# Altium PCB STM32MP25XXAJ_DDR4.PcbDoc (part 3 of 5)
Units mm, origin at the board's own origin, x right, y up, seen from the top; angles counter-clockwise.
Board outline 172 x 137 mm, 4 copper layers (Top Layer, Signal Layer 1, Signal Layer 2, Bottom Layer), stack 1.614 mm thick; 226 components, 313 nets, 1113 pads, 850 vias.
Unrouted connection lines stored in the file: 13.
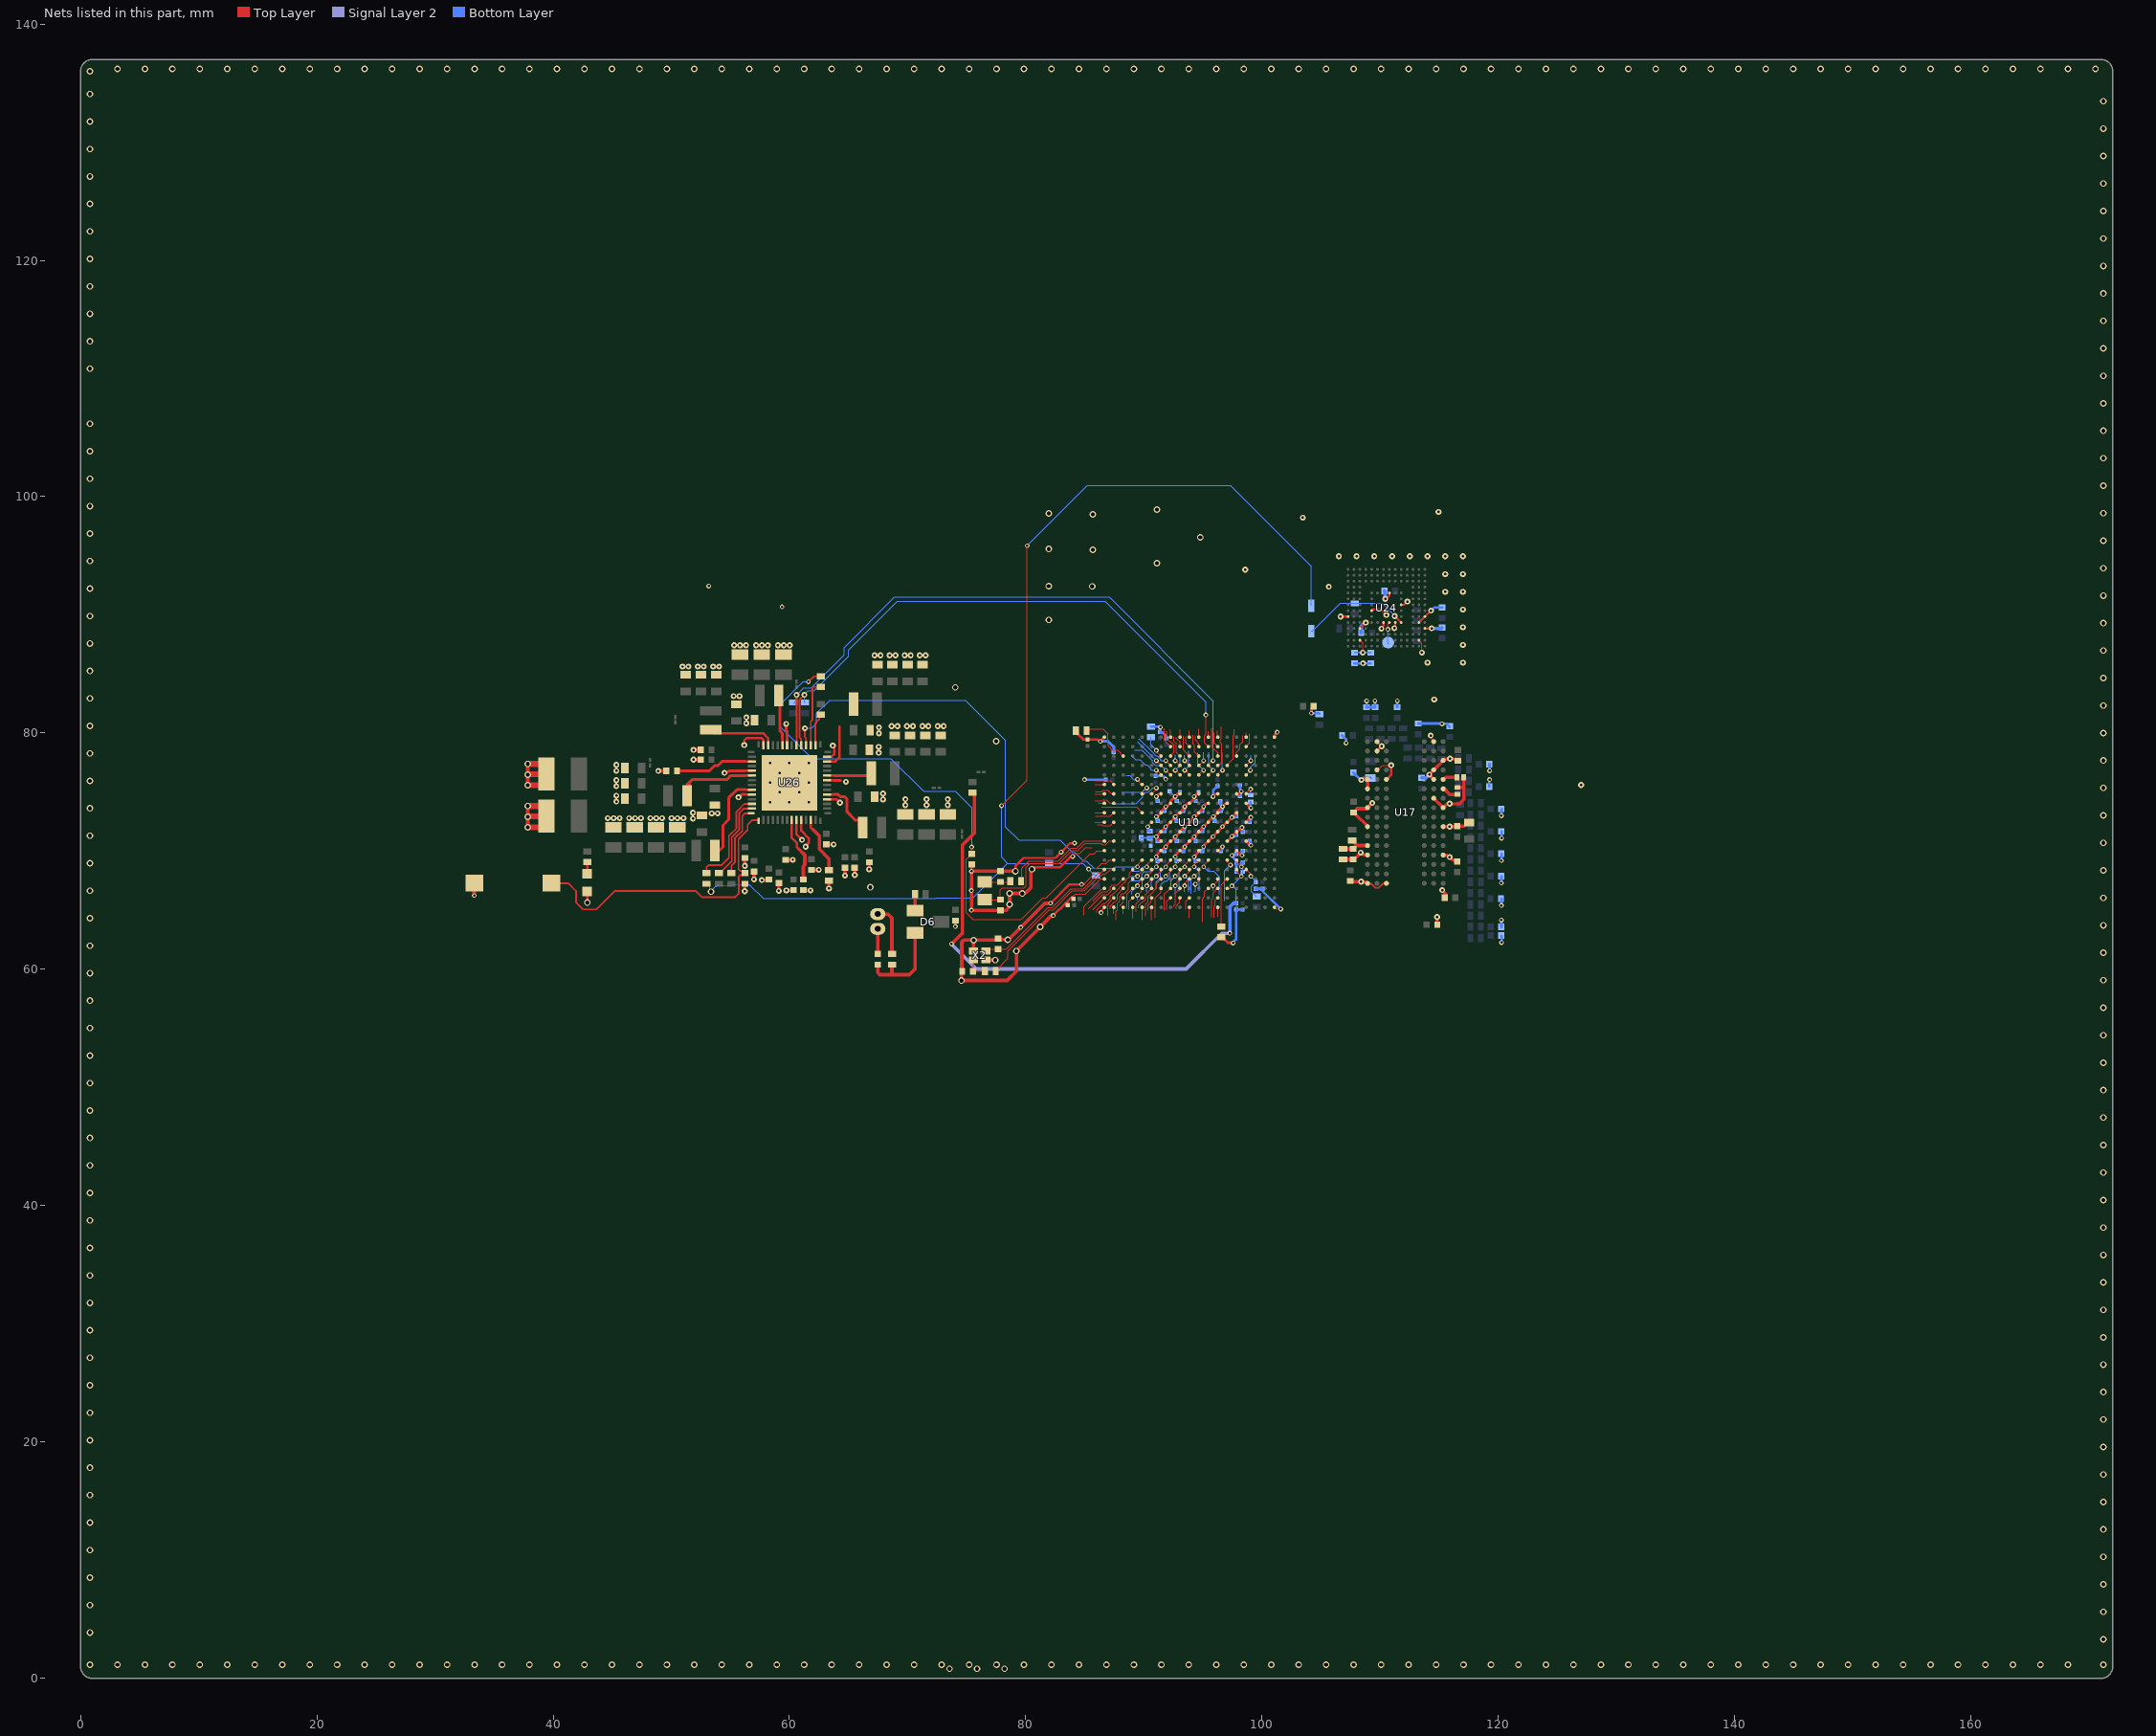
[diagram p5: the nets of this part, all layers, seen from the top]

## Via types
v1: diameter 0.55, hole 0.35, Top Layer to Bottom Layer, 344 vias
v2: diameter 0.5, hole 0.2, Top Layer to Bottom Layer, 250 vias
v3: diameter 0.4, hole 0.2, Top Layer to Bottom Layer, tented both sides, 180 vias
v4: diameter 0.4, hole 0.2, Top Layer to Bottom Layer, 76 vias

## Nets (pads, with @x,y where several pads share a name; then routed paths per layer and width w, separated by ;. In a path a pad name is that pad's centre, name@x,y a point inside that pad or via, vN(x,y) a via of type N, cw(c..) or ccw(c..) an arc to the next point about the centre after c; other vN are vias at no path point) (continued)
GND: B2.1 C18.2 C19.1 C20.1 C21.1 C22.1 C23.1 C24.1 C26.1 C27.1 C28.1 C29.1 C30.1 C32.1 C33.1 C34.1 C35.1 C36.1 C37.1 C38.1 C39.1 C40.1 C41.1 C42.2 C43.1 C67.1 C70.1 C79.1 C81.2 C82.1 C86.2 C87.1 C90.1 C91.2 C92.2 C94.1 C104.1 C105.1 C106.1 C112.1 C141.2 C142.2 C143.1 C144.1 C145.1 C146.1 C152.1 C153.1 C154.1 C155.1 C156.1 C157.1 C159.1 C160.1 C161.1 C163.1 C164.2 C165.1 C166.1 C167.1 C168.1 C169.1 C171.1 C172.1 C173.2 C174.2 C175.1 C176.1 C177.1 C178.1 C179.1 C180.1 C181.1 C182.1 C183.1 C184.1 C186.1 C187.1 C188.1 C189.1 C190.2 C191.2 C192.1 C193.1 C195.1 C196.1 C199.1 C200.1 C201.1 C202.1 C204.1 C206.1 C207.1 C208.2 C209.1 C210.1 C217.2 C218.1 C226.1 C239.1 C252.1 C254.1 C255.1 C256.1 C257.1 C258.1 C259.1 C261.1 C265.1 C266.1 C342.1 C344.1 C352.1 C353.1 C354.1 C355.1 C356.1 C357.1 C360.2 C372.1 C377.1 C378.1 C380.1 C381.1 C382.1 C383.1 C384.1 C386.1 C387.2 C388.1 C389.2 C390.1 C393.1 C399.2 C400.1 C402.1 C404.1 C406.1 C407.1 C408.1 C409.1 C417.1 C478.1 C479.1 C481.1 LD11.2 R57.1 R112.1 R113.1 R118.1 R161.2 R162.2 R176.1 R179.1 R196.1 U10.A1 U10.A19 U10.G7 U10.G9 U10.G11 U10.G13 U10.G15 U10.H8 U10.H10 U10.H12 U10.H14 U10.H16 U10.J7 U10.J9 U10.J11 U10.J13 U10.J15 U10.K8 U10.K10 U10.K12 U10.K14 U10.K16 U10.L7 U10.L9 U10.L11 U10.L13 U10.L15 U10.M7 U10.M8 U10.M10 U10.M12 U10.M14 U10.M16 U10.N7 U10.N9 U10.N11 U10.N13 U10.N15 U10.T1 U10.W1 U10.W19 U17.A2 U17.A8 U17.B2 U17.C9 U17.D2 U17.D8 U17.E1 U17.E3 U17.E8 U17.F1 U17.G8 U17.H1 U17.H9 U17.K1 U17.K9 U17.N1 U17.N9 U17.T1 U17.T3 U24.A6 U24.C4 U24.E7 U24.G5 U24.H10 U24.J5 U24.K8 U24.N2 U24.N5 U24.P4 U24.P6 U26.9 U26.10 U26.18 U26.22 U26.27 U26.36 U26.41 U26.47 U26.52 U26.57 X2.2 X2.4 | length 236.6
  Top Layer w0.09: U10.W19@101.05,65.25 101.058,65.25 101.208,65.1 v4(101.575,65.1) ; U24.N2@113.275,87.85 113.525,87.6 v2(113.525,86.8)
  Top Layer w0.1: v2@44.624,72.799 v2@44.625,72.8 ; X2.2@75.547,61.575 X2.2@75.548,61.576 ; v1@75.573,62.448 v1(75.587,62.462) v1@75.6,62.475 ; C406.1@83.9,66.1 84.185,66.385 85.068,66.385 86.333,67.65 U10.T1@86.65,67.65 ; v3(83.972,69.56) 84.237,69.825 84.544,69.825 85.034,70.315 85.6,70.315 ; 84.925,67.234 85.315,67.625 85.79,68.1 ; U17.D2@109.727,76.873 109.8,76.873 110.2,77.273 v2@110.927,77.273 ; v2(114.27,79.78) 114.27,79.672 114.37,79.572 114.37,79.494 114.525,79.339 U17.A8@114.525,79.275
  Top Layer w0.11: v4@86.291,64.884 U10.W1@86.65,65.244
  Top Layer w0.15: U17.T1@108.927,67.273 108.952,67.248 109.221,67.248 109.571,66.898 109.882,66.898 110.232,67.248 110.502,67.248 U17.T3@110.527,67.273
  Top Layer w0.18: v2(106.65,89.85) U24.A6@107.275,89.85 ; U24.C4@108.275,88.85 108.725,89.3 108.735,89.3 v2(108.775,89.34) ; U24.E7@109.275,90.35 109.283,90.35 109.416,90.483 110.028,90.483 110.516,89.995 v2(110.525,89.995) ; v2(110.1,88.825) 110.1,88.913 110.275,89.088 U24.G5@110.275,89.35 ; v2@110.425,91.275 110.775,91.625 U24.H10@110.775,91.85 ; v2(111.2,88.875) 111.2,88.962 111.275,89.037 U24.J5@111.275,89.35 ; U24.K8@111.775,90.85 112.025,90.85 v2(112.3,91.125) ; U24.N5@113.275,89.35 U24.P6@113.775,89.85 114.275,90.35 v2(114.3,90.35) ; U24.P4@113.775,88.85 v2(114.35,88.85)
  Top Layer w0.2: v1(42.887,65.648) LD11.2@42.887,66.577 ; U26.27@63.17,78 63.579,78 63.77,78.191 63.77,78.91 v2@63.816,78.956 ; v2(63.67,78.93) v2@63.727,78.873 ; C87.1@74.05,64.125 74.05,63.634 v3(74.051,63.633) ; v3(75.402,68.305) 75.416,68.319 C33.1@75.416,68.915 ; v1(79.125,68.3) 79.125,68.75 79.8,69.425 82.507,69.425 83.002,69.92 83.752,70.67 v4@84.121,70.67 ; v1(80.525,68.475) 80.62,68.475 80.795,68.65 82.912,68.65 83.784,69.522 v3@83.934,69.522 ; v3(82.1,65.6) 83.683,67.182 84.711,67.182 84.763,67.234 84.925,67.234 ; v3(82.325,64.55) 83.363,65.587 ; C67.1@83.55,65.425 83.525,65.425 83.363,65.587 ; C406.1@84.025,65.975 83.9,66.1 83.9,66.125 83.363,65.587 ; v4(91.05,69.525) 91.05,69.65 U10.N7@91.45,70.05 ; U10.N7@91.445,70.05 U10.N7@91.45,70.05 ; v3@91.85,70.438 91.462,70.05 U10.N7@91.45,70.05 ; v3@91.851,70.438 v3@91.863,70.438 ; v3(92.65,69.525) 92.709,69.584 92.709,69.709 U10.N9@93.05,70.05 93.125,70.05 v3(93.45,70.375) ; U17.E3@110.529,76.073 110.94,76.484 110.94,77.26 v2@110.927,77.273
  Top Layer w0.21: v2(56.175,78.975) 56.175,79.375 56.38,79.58 57.609,79.58 57.8,79.389 U26.41@57.8,78.97 ; 56.275,74.8 U26.52@56.83,74.8 ; 56.275,76.8 U26.47@56.83,76.8 ; U26.36@59.8,78.97 59.8,79.525 ; U26.9@60.6,72.63 60.6,71.42 v2(61.068,70.952) ; U26.10@61,72.63 61,71.734 61.635,71.099 61.635,70.72 61.37,70.456 v2(61.37,70.377) ; U26.18@63.17,74.4 63.972,74.4 v2(64.272,74.1) ; U26.22@63.17,76 63.725,76
  Top Layer w0.22: R162.2@84.25,80.2 84.395,80.055 84.395,79.914 84.854,79.455 85.22,79.455 C353.1@85.225,79.45 86.097,79.45 86.262,79.285 v4(86.31,79.285) 86.31,79.298 86.63,79.618 86.63,79.648 U10.A1@86.625,79.653 ; v3(91.05,71.225) 91.05,71.25 U10.L7@91.45,71.65 91.45,71.675 v3(91.85,72.075) ; v3(91.05,72.925) 91.084,72.959 91.164,72.959 U10.J7@91.45,73.245 ; v3@91.052,74.625 91.257,74.831 91.431,74.831 U10.G7@91.45,74.85 ; v3@91.07,71.146 91.112,71.146 91.393,70.865 91.393,70.85 U10.M7@91.445,70.85 ; U10.J7@91.45,73.25 91.465,73.265 91.465,73.404 v3@91.836,73.775 ; v3(91.85,70.375) 91.85,70.438 91.85,70.45 U10.M8@92.25,70.85 ; v3(91.85,73.775) 91.884,73.809 91.999,73.809 92.239,74.05 U10.H8@92.25,74.05 92.25,74.225 v3(92.65,74.625) 92.65,74.645 92.841,74.836 93.031,74.836 U10.G9@93.045,74.85 ; v3@91.875,72.075 U10.K8@92.25,72.45 92.65,72.85 v3(92.65,72.925) 92.65,72.939 92.894,73.183 92.926,73.183 92.993,73.25 U10.J9@93.05,73.25 93.425,73.625 v3@93.425,73.775 ; U10.M8@92.245,70.85 U10.M8@92.25,70.85 ; v4(92.65,71.225) 93.05,71.625 U10.L9@93.05,71.65 ; v4@92.698,71.18 92.637,71.18 92.307,70.85 U10.M8@92.25,70.85 ; U10.L9@93.045,71.65 93.348,71.954 93.441,71.954 93.441,72.046 U10.J11@94.647,73.253 ; v3(93.45,70.375) 93.45,70.45 U10.M10@93.85,70.85 93.875,70.85 v3(94.25,71.225) ; v3(93.45,73.775) 93.45,73.787 93.676,74.013 93.813,74.013 U10.H10@93.85,74.05 94.25,74.45 v3(94.25,74.625) 94.457,74.832 94.626,74.832 U10.G11@94.645,74.85 ; v3@94.225,69.525 94.65,69.95 U10.N11@94.65,70.05 ; v3@94.25,71.255 94.645,71.65 U10.L11@94.65,71.65 ; U10.J11@94.625,73.25 95.05,73.675 v3(95.05,73.775) 95.05,73.793 95.267,74.01 95.41,74.01 U10.H12@95.45,74.05 ; U10.L11@94.675,71.7 v4(95.05,72.075) ; v4(95.05,70.375) 95.084,70.409 95.084,70.484 U10.M12@95.45,70.85 95.825,71.225 v4(95.85,71.225) 95.85,71.253 U10.L13@96.247,71.65 ; v4@95.075,72.075 U10.K12@95.45,72.45 95.465,72.465 95.465,72.535 95.845,72.915 95.909,72.915 U10.J13@96.245,73.25 ; v3(95.85,74.625) 95.85,74.638 96.05,74.838 96.238,74.838 U10.G13@96.25,74.85 ; U10.N13@96.246,70.05 96.325,70.05 v3(96.65,70.375) ; U10.L13@96.25,71.661 v4@96.65,72.061 ; U10.J13@96.25,73.25 96.25,73.375 v3(96.65,73.775) ; R196.1@96.55,62.725 96.645,62.725 97.111,62.259 97.516,62.259 v4(97.55,62.225) ; v4(96.65,72.075) 97.025,72.45 U10.K14@97.05,72.45 ; v3@96.65,73.781 96.878,74.01 97.01,74.01 U10.H14@97.05,74.05 ; U10.M14@97.052,70.85 v3@97.45,71.248 ; U10.K14@97.052,72.45 v4@97.45,72.848 ; v4@97.45,72.854 U10.J15@97.846,73.25 ; v3@97.484,71.284 U10.L15@97.85,71.65 97.9,71.65 v3@98.25,72 ; U10.N15@97.835,70.035 U10.N15@97.85,70.05 ; U10.N15@97.85,70.049 v4@98.249,69.65 ; U10.G15@97.85,74.85 98.04,74.85 v3(98.25,75.06) ; U10.K16@98.65,72.45 v3(99.05,72.85) ; U10.H16@98.65,74.05 v3(99.05,73.65) ; U10.M16@98.652,70.85 99.002,70.5 v3(99.05,70.5) ; U10.A19@101.05,79.65 101.065,79.665 101.065,79.818 101.268,80.021 v4(101.268,80.062) ; v4(104.175,81.675) 104.175,82.05 C70.1@104.375,82.25 ; U17.B2@109.725,78.475 v2(110.125,78.875) U17.A2@109.725,79.275
  Top Layer w0.25: v2(54.508,76.625) 54.556,76.673 54.757,76.673 54.884,76.8 56.275,76.8 ; v2(55.687,74.563) 55.721,74.563 55.959,74.8 56.275,74.8 ; v2(59.725,80.775) 59.725,80.214 59.8,80.139 59.8,79.525 ; 63.725,76 64.33,76 ; v2@64.257,74.1 v2(64.272,74.1)
  Top Layer w0.28: C105.1@107.89,73.142 108.925,72.107 U17.K1@108.925,72.075 ; v2@108.377,76.073 108.927,76.073 U17.F1@108.927,75.273 ; U17.G8@114.525,74.475 U17.H9@115.325,73.675 115.674,74.025 v2(115.875,74.025) ; U17.E8@114.537,76.083 114.529,76.083 114.15,76.462 v2(114.15,76.475) 114.15,76.488 114.527,76.864 114.527,76.873 115.327,77.673 115.365,77.673 115.472,77.781 115.788,77.781 v2@115.83,77.823 ; C82.1@114.812,63.768 v2@114.812,64.413 ; U17.N9@115.327,69.673 115.353,69.646 115.669,69.646 v2@115.817,69.498 ; U17.K9@115.327,72.073 v2@115.877,72.073 ; v2@115.825,74 116.7,74 117.075,74.375 117.075,75.4 ; v2@115.877,69.498 115.886,69.498 116.151,69.233 116.402,69.233 C252.1@116.515,69.12 C252.1@116.515,69.12 ; v2@115.877,77.823 115.902,77.823 v2(115.9,77.825) 115.917,77.809 116.271,77.809 116.315,77.765 116.46,77.765 C178.1@116.575,77.65 ; v2@115.915,72.035 v2@115.877,72.073 ; R179.1@116.525,75.4 117.075,75.4 ; R113.1@117.075,76.25 117.075,75.4 ; C112.1@117.547,72.428 117.422,72.428 117.112,72.118 116.517,72.118 116.494,72.096 115.899,72.096 v2@115.877,72.073
  Top Layer w0.3: v3(33.319,66.245) 33.324,66.25 33.324,67.279 B2.1@33.34,67.295 ; v1(37.848,72.014) v1(37.848,72.914) v1(37.848,73.814) ; v1(37.848,75.576) v1(37.848,76.476) v1(37.848,77.376) ; v2(48.895,76.79) C43.1@49.555,76.79 ; v2(51.885,77.75) C40.1@52.495,77.75 ; v2(51.885,78.575) C39.1@52.495,78.575 ; v2@56.225,68.81 C217.2@56.225,69.42 ; v2@56.227,66.58 C155.1@56.227,67.185 ; v2(57,67.61) C154.1@57,68.215 ; v2(57.665,67.55) C142.2@58.275,67.55 ; v2@59.1,66.69 C141.2@59.1,67.3 ; C153.1@59.675,69.27 v2(60.285,69.27) ; v2(59.74,66.68) C91.2@60.35,66.68 ; C208.2@61.175,66.68 v2(61.785,66.68) ; C209.1@61.85,68.42 v2(62.485,68.42) ; C156.1@63.125,70.57 v2(63.735,70.57) ; v2(63.35,66.84) R57.1@63.35,67.5 ; v2(64.7,67.93) C189.1@64.7,68.59 ; v2(65.525,67.99) C188.1@65.525,68.59 C188.1@65.525,68.65 ; v2@66.75,68.465 66.747,68.467 66.747,69.063 C190.2@66.75,69.065 ; C92.2@74.563,59.875 74.563,59.087 74.588,59.063 78.438,59.063 79.225,59.85 79.225,61.525 v1(79.2,61.55) 81.225,63.575 v1(81.225,63.6) 82.156,64.531 82.306,64.531 v3(82.325,64.55) ; C92.2@74.625,59.825 74.576,59.874 74.576,62.299 74.752,62.475 75.6,62.475 76,62.475 76.013,62.488 76.663,62.488 76.675,62.475 77.5,62.475 77.625,62.6 C90.1@77.65,62.6 77.736,62.514 v1@78.475,62.514 ; v3(75.4,65) C86.2@77.85,65 ; 75.4,65.275 v3@75.4,66.65 ; v3@75.4,68.3 v3@75.402,68.3 ; v3(75.402,66.655) v3@75.402,68.3 ; v3(75.402,68.305) v3@75.402,68.3 ; X2.2@75.573,61.551 v1@75.573,62.448 ; X2.4@76.66,60.788 76.667,60.794 77.408,60.794 v1(77.415,60.788) ; C86.2@77.955,65.105 C86.2@77.85,65 ; v1(78.475,62.5) 78.525,62.5 v3(79.575,63.55) 81.606,65.581 v3@82.081,65.581 ; v1(79.125,68.3) C81.2@77.85,68.3 v3@75.402,68.3 ; v1(80.525,68.475) 80.43,68.38 80.43,66.905 79.993,66.468 79.748,66.468 v1(79.7,66.42) 79.695,66.425 v1(78.625,66.425) v1(78.625,65.5) 78.578,65.452 78.578,65.239 78.339,65 C86.2@77.85,65 ; R118.1@106.857,69.298 107.727,69.298 107.832,69.403 107.88,69.403 v2@108.354,69.877 ; C104.1@107.397,67.408 107.412,67.423 108.387,67.423 108.425,67.385 108.782,67.385 108.894,67.273 U17.T1@108.927,67.273 ; C105.1@107.737,73.278 C105.1@107.89,73.278 ; C105.1@107.75,73.275 107.775,73.275 107.88,73.38 107.88,73.405 108.07,73.595 108.812,73.595 108.89,73.673 108.927,73.673 v2@109.327,74.073 ; v2@108.355,69.878 108.409,69.878 108.591,69.696 108.904,69.696 U17.N1@108.925,69.675 U17.N1@108.927,69.673 ; v2(115.25,66.7) 115.25,66.646 115.552,66.344 C106.1@115.552,66.198
  Top Layer w0.5: v1(37.848,72.014) 39.39,72.014 C18.2@39.437,72.061 ; v1(37.848,72.914) 37.862,72.914 37.909,72.961 C18.2@39.437,72.961 ; v1(37.848,73.814) C18.2@39.379,73.814 ; v1(37.848,75.576) 39.39,75.576 C42.2@39.437,75.623 ; v1(37.848,76.476) 37.862,76.476 37.909,76.523 C42.2@39.437,76.523 ; v1(37.848,77.376) C42.2@39.379,77.376
  Bottom Layer w0.09: C404.1@99.95,66.725 C404.1@99.95,66.825
  Bottom Layer w0.1: C79.1@89.6,70.975 C79.1@89.689,70.975 ; C171.1@92.175,75.075 92.625,74.625 v3(92.65,74.625) ; v3@92.625,74.65 v3@92.7,74.65
  Bottom Layer w0.2: C79.1@89.75,71.125 90.5,71.125 90.525,71.1 C384.1@90.55,71.075 ; v4(91.05,69.525) 91.05,69.275 C399.2@91.175,69.15 ; v3(92.65,69.525) 92.65,69.25 C400.1@92.775,69.125 ; C404.1@99.95,66.725 v4(101.575,65.1) ; C182.1@107.825,85.9 v2(108.55,85.9) 109.175,85.9 C481.1@109.2,85.875 ; v2(114.3,90.35) 114.575,90.625 C478.1@115.225,90.625 C478.1@115.25,90.625
  Bottom Layer w0.22: v4@84.95,76.05 C161.1@86.775,76.05 ; v4(86.31,79.285) 86.325,79.3 86.95,79.3 87.45,78.8 C356.1@87.45,78.4 ; C384.1@90.5,71.075 90.65,71.225 v3(91.05,71.225) ; R161.2@90.6,80.55 91.35,80.55 v4@91.4,80.5 ; v4@90.975,69.5 v4@91.025,69.5 ; C344.1@90.975,76.375 91.575,76.375 v4(91.85,76.1) ; v3@91.016,71.191 v3(91.05,71.225) ; v3(91.05,72.925) 91.05,72.7 C169.1@91.2,72.55 ; v3(91.05,74.625) 91.05,74.576 91.11,74.516 91.11,74.315 C166.1@91.175,74.25 ; C387.2@91.175,70.85 91.05,70.975 v3(91.05,71.225) ; v4(91.403,80.496) 91.403,80.047 91.415,80.035 91.596,80.035 91.835,79.796 91.835,79.615 C352.1@91.9,79.55 ; C393.1@91.725,70.025 91.85,70.15 v3(91.85,70.375) ; C378.1@91.725,71.7 91.85,71.825 v3(91.85,72.075) ; C173.2@91.725,73.425 91.85,73.55 v3(91.85,73.775) ; v4(92.65,71.225) 92.65,70.975 C380.1@92.775,70.85 ; v3(92.65,72.925) 92.65,72.675 C164.2@92.775,72.55 ; C390.1@92.775,74.275 92.65,74.4 v3(92.65,74.625) 92.675,74.625 92.7,74.65 C143.1@93.05,75 ; C192.1@93.325,70 93.45,70.125 v3(93.45,70.375) ; C372.1@93.325,71.7 93.45,71.825 v3(93.45,72.075) ; C167.1@93.325,73.4 93.45,73.525 v3(93.45,73.775) ; v3(94.25,69.525) 94.25,69.275 C402.1@94.375,69.15 C402.1@94.4,69.125 ; v3(94.25,71.225) 94.25,70.975 C382.1@94.375,70.85 ; v4(94.25,72.925) 94.25,72.675 C168.1@94.375,72.55 ; v3(94.25,74.625) 94.25,74.375 C360.2@94.375,74.25 ; C381.1@94.925,70 95.05,70.125 v4(95.05,70.375) ; C388.1@94.925,71.7 95.05,71.825 v4(95.05,72.075) ; C159.1@94.925,73.4 95.05,73.525 v3(95.05,73.775) ; v3(95.85,74.625) 95.85,75.125 C354.1@96.225,75.5 ; v3(95.875,72.925) 95.875,72.65 C163.1@95.975,72.55 ; C165.1@96.475,74.225 96.475,73.95 v3(96.65,73.775) 96.65,73.525 C174.2@96.525,73.4 ; C191.2@96.525,70.025 96.65,70.15 v3(96.65,70.375) ; v4(97.45,72.85) 97.7,72.85 C201.1@97.825,72.975 C201.1@97.85,73 ; v3(97.45,71.25) 97.7,71.25 C377.1@97.825,71.375 ; v4(97.55,62.225) 97.55,62.274 97.8,62.524 C407.1@97.8,65.05 C210.1@98.35,65.05 ; C386.1@97.802,69.752 97.76,69.71 97.559,69.71 97.499,69.65 v3(97.45,69.65) 97.484,69.616 97.484,69.529 97.76,69.253 97.76,69.115 97.825,69.05 97.825,68.275 C417.1@97.85,68.25 ; C176.1@98.125,74.675 98.19,74.74 98.19,74.951 98.25,75.011 v3(98.25,75.06) 98.125,75.185 C357.1@98.125,75.575 C357.1@98.125,75.6 ; v4@98.25,69.65 98.25,69.9 C195.1@98.375,70.025 ; v3(98.3,72) 98.334,71.966 98.334,71.69 C383.1@98.399,71.625 ; C389.2@98.925,70.875 99.05,70.75 v3(99.05,70.5) ; C175.1@98.925,72.475 99.05,72.6 v3(99.05,72.85) ; R112.1@99.028,74.15 99.028,73.622 v3@99.05,73.6 ; v4(104.175,81.675) 104.8,81.675 R176.1@104.85,81.625 ; C255.1@106.775,79.8 106.775,79.775 106.92,79.63 106.945,79.63 107.109,79.466 107.109,79.166 v4(107.114,79.161) ; C218.1@107.725,76.65 108.35,76.025 v2(108.395,76.025) v2@108.4,76.025 ; v2@108.425,76.025 108.6,76.2 C172.1@109.175,76.2 ; C145.1@108.825,82.175 C145.1@108.85,82.175 ; v4(108.85,82.725) C145.1@108.85,82.175 ; v4(109.55,82.725) 109.562,82.713 109.562,82.188 C144.1@109.575,82.175 C145.1@108.85,82.175 ; C258.1@111.425,82.175 111.437,82.187 111.437,82.712 v4(111.45,82.725) ; C256.1@113.225,80.8 115.15,80.8 v4@115.2,80.75 ; v4(115.225,80.775) 115.625,80.775 C146.1@115.875,80.525 ; C257.1@119.225,75.475 119.225,75.975 v4@119.275,76.025 ; v4(119.25,76.8) C259.1@119.25,77.375 ; C254.1@120.25,62.825 120.275,62.8 v4(120.275,62.275) ; v4(120.25,64.175) C160.1@120.25,63.6 C160.1@120.275,63.575 ; v4(120.25,65.4) C226.1@120.25,65.975 ; v4(120.25,67.3) 120.25,67.85 C266.1@120.275,67.875 ; v4(120.25,69.2) 120.275,69.225 C239.1@120.275,69.75 ; v4(120.25,73) 120.25,73.5 C261.1@120.3,73.55 ; v4(120.275,71.1) C265.1@120.275,71.675
  Bottom Layer w0.28: C408.1@99.475,66.8 C404.1@100.025,66.8 ; C404.1@99.95,66.825 C404.1@99.975,66.825 ; C179.1@113.5,76.2 113.875,76.2 v2(114.15,76.475)
  Bottom Layer w0.3: C180.1@108.4,88.475 108.4,89.049 108.643,89.292 108.727,89.292 v2(108.775,89.34) ; C177.1@110.35,92.025 110.425,91.95 v2@110.425,91.275 ; v2(114.35,88.85) 115.15,88.85 C479.1@115.225,88.925
  other v1: 73.55,0.8 75.875,0.8 78.2,0.8 0.8,1.15 3.125,1.15 5.45,1.15 7.775,1.15 10.1,1.15 12.425,1.15 14.75,1.15 17.075,1.15 19.4,1.15 21.725,1.15 24.05,1.15 26.375,1.15 28.7,1.15 31.025,1.15 33.35,1.15 35.675,1.15 38,1.15 40.325,1.15 42.65,1.15 44.975,1.15 47.3,1.15 49.625,1.15 51.95,1.15 54.275,1.15 56.6,1.15 58.925,1.15 61.25,1.15 63.575,1.15 65.9,1.15 68.225,1.15 70.55,1.15 72.875,1.15 75.2,1.15 77.525,1.15 79.85,1.15 82.175,1.15 84.5,1.15 86.825,1.15 89.15,1.15 91.475,1.15 93.8,1.15 96.125,1.15 98.45,1.15 100.775,1.15 103.1,1.15 105.425,1.15 107.75,1.15 110.075,1.15 112.4,1.15 114.725,1.15 117.05,1.15 119.375,1.15 121.7,1.15 124.025,1.15 126.35,1.15 128.675,1.15 131,1.15 133.325,1.15 135.65,1.15 137.975,1.15 140.3,1.15 142.625,1.15 144.95,1.15 147.275,1.15 149.6,1.15 151.925,1.15 154.25,1.15 156.575,1.15 158.9,1.15 161.225,1.15 163.55,1.15 165.875,1.15 168.2,1.15 171.2,1.15 171.2,3.3 0.8,3.875 171.2,5.625 0.8,6.2 171.2,7.95 0.8,8.525 171.2,10.275 0.8,10.85 171.2,12.6 0.8,13.175 171.2,14.925 0.8,15.5 171.2,17.25 0.8,17.825 171.2,19.575 0.8,20.15 171.2,21.9 0.8,22.475 171.2,24.225 0.8,24.8 171.2,26.55 0.8,27.125 171.2,28.85 0.8,29.45 171.2,31.175 0.8,31.775 171.2,33.5 0.8,34.1 171.2,35.825 0.8,36.425 171.2,38.15 0.8,38.75 171.2,40.475 0.8,41.075 171.2,42.8 0.8,43.4 171.2,45.125 0.8,45.725 171.2,47.45 0.8,48.05 171.2,49.775 0.8,50.375 171.2,52.1 0.8,52.7 171.2,54.425 0.8,55.025 171.2,56.75 0.8,57.35 74.563,59.05 171.2,59.075 0.8,59.675 171.2,61.4 0.8,62 171.2,63.725 0.8,64.325 171.2,66.05 0.8,66.65 66.85,66.945 171.2,68.375 0.8,68.975 171.2,70.7 0.8,71.3 171.2,73.025 0.8,73.625 171.2,75.35 0.8,75.95 171.2,77.675 0.8,78.275 77.495,79.305 171.2,80 0.8,80.6 171.2,82.325 0.8,82.925 74.035,83.865 171.2,84.65 0.8,85.25 171.2,86.975 0.8,87.575 171.2,89.3 81.95,89.575 0.8,89.9 171.2,91.625 0.8,92.225 85.625,92.4 81.941,92.431 171.2,93.95 91.1,94.375 0.8,94.55 85.675,95.5 81.95,95.575 171.2,96.275 94.775,96.55 0.8,96.875 85.675,98.5 81.95,98.575 171.2,98.6 91.1,98.9 0.8,99.2 171.2,100.925 0.8,101.525 171.2,103.25 0.8,103.85 171.2,105.575 0.8,106.175 171.2,107.9 171.2,110.225 0.8,110.825 171.2,112.55 0.8,113.15 171.2,114.875 0.8,115.475 171.2,117.2 0.8,117.8 171.2,119.525 0.8,120.125 171.2,121.85 0.8,122.45 171.2,124.175 0.8,124.775 171.2,126.5 0.8,127.1 171.2,128.825 0.8,129.425 171.2,131.15 0.8,131.75 171.2,133.475 0.8,134.075 0.8,136 3.125,136.2 5.45,136.2 7.775,136.2 10.1,136.2 12.425,136.2 14.75,136.2 17.075,136.2 19.4,136.2 21.725,136.2 24.05,136.2 26.375,136.2 28.7,136.2 31.025,136.2 33.35,136.2 35.675,136.2 38,136.2 40.325,136.2 42.65,136.2 44.975,136.2 47.3,136.2 49.625,136.2 51.95,136.2 54.275,136.2 56.6,136.2 58.925,136.2 61.25,136.2 63.575,136.2 65.9,136.2 68.225,136.2 70.55,136.2 72.875,136.2 75.2,136.2 77.525,136.2 79.85,136.2 82.175,136.2 84.5,136.2 86.825,136.2 89.15,136.2 91.475,136.2 93.8,136.2 96.125,136.2 98.45,136.2 100.775,136.2 103.1,136.2 105.425,136.2 107.75,136.2 110.075,136.2 112.4,136.2 114.725,136.2 117.05,136.2 119.375,136.2 121.7,136.2 124.025,136.2 126.35,136.2 128.675,136.2 131,136.2 133.325,136.2 135.65,136.2 137.975,136.2 140.3,136.2 142.625,136.2 144.95,136.2 147.275,136.2 149.6,136.2 151.925,136.2 154.25,136.2 156.575,136.2 158.9,136.2 161.225,136.2 163.55,136.2 165.875,136.2 168.2,136.2 170.525,136.2
  other v2: 114.815,64.42 56.222,66.61 59.1,66.64 108.385,67.425 66.745,68.46 56.225,68.76 115.875,69.5 108.345,69.872 115.875,72.075 51.825,72.75 44.624,72.798 45.125,72.798 45.626,72.798 46.424,72.798 46.925,72.798 47.426,72.798 48.224,72.798 48.725,72.798 49.226,72.798 50.024,72.798 50.525,72.798 51.026,72.798 53.424,73.202 53.925,73.202 51.825,73.25 69.804,73.9 71.604,73.9 73.404,73.9 109.325,74.075 58.35,74.15 60,74.15 61.65,74.15 45.35,74.2 67.92,74.375 69.804,74.401 71.604,74.401 73.404,74.401 45.35,74.7 67.92,74.875 59.175,74.975 60.825,74.975 45.35,75.5 127,75.6 58.35,75.8 60,75.8 61.65,75.8 64.78,75.875 45.35,76 59.175,76.625 60.825,76.625 45.35,76.8 110.925,77.275 45.35,77.3 58.35,77.45 60,77.45 61.65,77.45 67.55,78.325 67.55,78.825 67.575,79.975 67.575,80.475 68.65,80.575 69.15,80.575 69.95,80.575 70.45,80.575 71.25,80.575 71.75,80.575 72.55,80.575 73.05,80.575 56.35,80.823 56.35,81.323 114.562,82.831 55.275,83.123 55.776,83.123 50.95,85.623 51.451,85.623 52.25,85.623 52.751,85.623 53.55,85.623 54.051,85.623 114,85.95 117,85.95 67.2,86.575 67.7,86.575 68.475,86.575 68.975,86.575 69.75,86.575 70.25,86.575 71.025,86.575 71.525,86.575 55.324,87.425 55.825,87.425 56.326,87.425 57.174,87.425 57.675,87.425 58.176,87.425 59.024,87.425 59.525,87.425 60.026,87.425 117,87.45 117,88.95 117,90.45 110.425,91.35 115.5,91.95 117,91.95 105.65,92.375 115.5,93.45 117,93.45 98.575,93.825 106.5,94.95 108,94.95 109.5,94.95 111,94.95 112.5,94.95 114,94.95 115.5,94.95 117,94.95 103.45,98.225 114.936,98.709
  other v3: 83,69.925 59.375,90.675 53.175,92.437
  other v4: 86.375,64.8 84.725,67.196 98.3,69.65 84.133,70.682 84.975,76.05 119.25,76.05
HSE_IN: C90.2 U10.R1 X2.1 | length 12.9
  Top Layer w0.1: X2.1@76.623,61.551 76.772,61.7 C90.2@77.65,61.7 78.35,61.7 81.9,65.25 82.245,65.25 83.828,66.832 84.877,66.832 86.184,68.14 86.338,68.14 U10.R1@86.648,68.45
HSE_OUT: R3.2 U10.R2 | length 14.1
  Top Layer w0.1: R3.2@77.375,59.725 77.58,59.93 77.58,60.027 78.5,60.947 78.5,61.567 81.983,65.05 82.328,65.05 83.91,66.632 84.96,66.632 86.267,67.94 86.421,67.94 86.531,68.05 86.748,68.05 87.148,68.45 U10.R2@87.45,68.45
I2C7.SCL: R261.1 U10.B12 U26.33 | length 50.2
  Top Layer w0.1: v4(95.25,81.525) 95.25,79.874 95.15,79.774 95.15,79.15 U10.B12@95.45,78.85
  Top Layer w0.15: U26.33@61,78.97 61,79.5 60.85,79.65 60.85,82.813 v2(61.262,83.225)
  Bottom Layer w0.1: v2@61.268,83.22 61.268,82.625 R261.1@61.305,82.588 ; v2@61.268,83.23 61.268,83.265 61.578,83.575 62.089,83.575 65.019,86.505 65.019,87.016 69.143,91.14 86.723,91.14 95.25,82.613 v4(95.25,81.525)
I2C7.SDA: R260.1 U10.D12 U26.34 | length 53.4
  Top Layer w0.09: U10.D12@95.445,77.25 95.445,77.296 95.748,77.599 v3@95.748,77.645
  Top Layer w0.15: U26.34@60.6,78.97 v2(60.6,83.225)
  Bottom Layer w0.09: v3(95.85,77.65) 95.873,77.673 95.873,82.702
  Bottom Layer w0.1: R260.1@60.33,82.58 60.42,82.58 60.6,82.76 v2(60.6,83.225) ; v2@60.613,83.225 61.202,83.814 61.833,83.814 64.619,86.6 64.619,87.231 68.901,91.513 87.062,91.513 95.873,82.702
JTCK_SWCLK: U10.V1 | length 1.4
  Top Layer w0.09: 85.682,65.06 86.65,66.028 U10.V1@86.65,66.05
JTDI: U10.W2 | length 0.5
  Top Layer w0.09: 87.45,64.7 U10.W2@87.45,65.25
JTDO_SWDO: U10.U1 | length 3.1
  Top Layer w0.1: 84.925,64.588 84.925,65.303 86.397,66.775 86.521,66.775 86.596,66.85 U10.U1@86.65,66.85
JTMS_SWDIO: U10.V2 | length 1.7
  Top Layer w0.09: 86.945,64.563 86.945,65.372 86.935,65.382 86.935,65.517 87.45,66.032 U10.V2@87.45,66.05
LVDS1_D0N: U10.F2 | length 1.7
  Top Layer w0.09: 85.85,75.96 87.14,75.96 U10.F2@87.45,75.65
LVDS1_D0P: U10.F1 | length 0.8
  Top Layer w0.09: 85.875,75.65 U10.F1@86.65,75.65
LVDS1_D1N: U10.G2 | length 1.7
  Top Layer w0.09: 85.881,75.049 86.432,75.049 86.534,75.151 86.95,75.151 87.239,74.862 87.438,74.862 U10.G2@87.45,74.85
LVDS1_D1P: U10.G1 | length 0.8
  Top Layer w0.09: 85.875,74.85 U10.G1@86.65,74.85
LVDS1_D2N: U10.H2 | length 1.7
  Top Layer w0.09: 85.865,74.26 86.443,74.26 86.528,74.345 86.837,74.345 87.132,74.05 U10.H2@87.45,74.05
LVDS1_D2P: U10.H1 | length 0.5
  Top Layer w0.09: 86.124,74.046 U10.H1@86.646,74.046
LVDS1_D3N: U10.K2 | length 1.5
  Top Layer w0.09: 86.061,72.251 86.432,72.251 86.518,72.165 87.165,72.165 U10.K2@87.45,72.45
LVDS1_D3P: U10.K1 | length 0.8
  Top Layer w0.09: 85.875,72.45 U10.K1@86.65,72.45
LVDS1_D4N: U10.J2 | length 1.7
  Top Layer w0.09: 85.902,72.952 87.152,72.952 U10.J2@87.45,73.25
LVDS1_D4P: U10.J1 | length 0.8
  Top Layer w0.09: 85.875,73.25 U10.J1@86.65,73.25
MP257_WAKEUP: U10.P5 U26.32 | length 41.9
  Top Layer w0.09: v3@89.445,68.85 U10.P5@89.845,69.25
  Top Layer w0.15: v2(61.3,80.4) 61.3,79.653 61.4,79.553 U26.32@61.4,78.97
  Bottom Layer w0.09: 78.3,72.05 79.4,70.95 82.9,70.95 83.945,69.905 84.158,69.905 84.885,69.178 85.12,69.178 85.763,68.535 87.46,68.535 87.6,68.675 v3(89.45,68.675)
  Bottom Layer w0.1: v2(61.3,80.4) 61.881,80.4 62.3,80.819 62.3,81.657 63.418,82.775 74.895,82.775 78.295,79.375 78.295,72.05
NetB2_2: B2.2 C155.2 U26.1 | length 26.2
  Top Layer w0.15: B2.2@39.882,67.292 41.271,67.292 41.933,66.63 41.933,65.666 42.532,65.067 43.658,65.067 45.208,66.618 52.086,66.618 52.59,66.114 55.417,66.114 55.696,66.393 55.696,67.818 ; 55.7,67.825 55.847,67.972 56.054,67.972 C155.2@56.227,68.145 56.062,68.31 55.838,68.31 55.687,68.46 55.687,71.008 56.462,71.783 56.462,72.237 56.855,72.63 U26.1@57.4,72.63
NetC43_2: C43.2 U26.45 | length 6.7
  Top Layer w0.21: 56.275,77.6 U26.45@56.83,77.6
  Top Layer w0.25: C43.2@50.515,76.79 53.231,76.79 53.676,77.235 53.951,77.235 54.316,77.6 56.275,77.6
NetC81_1: C81.1 R64.2 X1.1 | length 2.2
  Top Layer w0.1: X1.1@76.525,67.4 78.65,67.4 R64.2@78.7,67.45
NetC88_1: C88.1 CN12.2 | length 2.1
  Top Layer w0.3: C88.1@67.475,61.3 CN12.2@67.475,63.425
NetC88_2: C88.2 D6.2 R66.2 | length 8
  Top Layer w0.3: C88.2@67.475,60.4 67.475,59.726 67.651,59.55 68.675,59.55 ; R66.2@68.675,60.395 68.675,59.55 ; D6.2@70.625,63.075 70.625,60.025 70.15,59.55 68.675,59.55
NetC92_1: C92.1 R3.1 X2.3 | length 1.9
  Top Layer w0.1: X2.3@75.573,60.801 75.573,59.877 75.548,59.852 75.55,59.85 76.35,59.85 R3.1@76.475,59.725
NetC94_2: C94.2 R116.2 R118.2 U17.M1 | length 2.8
  Top Layer w0.3: R118.2@106.857,70.198 107.727,70.198 107.957,70.428 107.957,70.578 107.827,70.708 107.827,70.803 107.722,70.908 R116.2@107.627,70.908 ; 108.027,70.473 U17.M1@108.927,70.473
NetC182_2: C182.2 C481.2 U24.C2 | length 2.6
  Top Layer w0.09: U24.C2@108.275,87.85 108.525,87.6 v2(108.525,86.8)
  Bottom Layer w0.11: C182.2@107.825,86.8 v2(108.525,86.8) C481.2@109.2,86.8 C481.2@109.225,86.775
NetC208_1: C208.1 U26.8 | length 5.4
  Top Layer w0.21: U26.8@60.2,72.63 60.2,71.134 60.625,70.709 60.625,70.345 60.798,70.173
  Top Layer w0.3: 60.798,70.173 61.3,69.67 61.3,68.843 61.175,68.718 C208.1@61.175,67.705
NetC384_2: C384.2 U10.K6 | length 1
  Top Layer w0.09: v3@90.262,72.063 U10.K6@90.65,72.45
  Bottom Layer w0.2: v3(90.325,72.075) 90.363,72.037 90.363,71.775 90.463,71.675 C384.2@90.5,71.675
NetC407_2: C407.2 C409.2 C417.2 R199.2 U10.P15 U10.R15 U10.U14 | length 48.1
  Top Layer w0.1: U10.U14@97.05,66.85 97.225,66.85 v3(97.45,67.075) ; U10.R15@97.85,68.45 97.85,68.275 v3(98.25,67.875) ; U10.P15@97.85,69.25 97.85,69.075 v3(98.25,68.675)
  Top Layer w0.3: v3(73.725,62.15) 74.647,63.072 74.647,70.522 75.65,71.525 75.65,74.8 R199.2@75.5,74.95
  Signal Layer 2 w0.3: v3(73.725,62.15) 73.725,62.124 75.823,60.026 93.576,60.026 96.599,63.049 v4@97.289,63.049
  Bottom Layer w0.1: C407.2@97.8,65.6 97.8,66.763 97.488,67.075 v3(97.45,67.075) v3(98.25,67.875) 98.375,68 C417.2@98.375,68.25 ; C417.2@98.375,68.275 v3@98.375,68.55
  Bottom Layer w0.3: v4(97.275,63.05) 97.275,65.297 97.553,65.575 97.775,65.575 C407.2@97.8,65.6 ; v3@98.275,68.675 98.275,68.955 C409.2@98.377,69.057
NetC408_2: C408.2 R197.2 U10.R16 | length 2.9
  Top Layer w0.1: U10.R16@98.65,68.45 99.05,68.05 v3(99.05,67.875)
  Bottom Layer w0.1: v3(99.05,67.875) 99.35,67.575 99.35,67.5 C408.2@99.45,67.4 ; C408.2@99.475,67.375 99.35,67.25 99.332,67.25 99.1,67.018 99.1,66.575 R197.2@99.525,66.15
NetCN12_1: CN12.1 R66.1 | length 4.4
  Top Layer w0.3: CN12.1@67.475,64.675 68.344,64.675 68.675,64.344 R66.1@68.675,61.295
NetD5_1: D5.1 R248.1 U24.K5 | length 9.2
  Top Layer w0.18: v2(111.225,89.9) U24.K5@111.775,89.35
  Bottom Layer w0.1: D5.1@104.175,88.63 D5.1@104.25,88.63 ; D5.1@104.25,88.6 106.625,90.975 R248.1@107.85,90.975 110.175,90.975 v2@111.2,89.95
NetD6_1: D6.1 R67.1 | length 1.4
  Top Layer w0.3: D6.1@70.625,64.975 R67.1@70.625,66.375
NetL1_1: L1.1 U26.37 | length 4.2
  Top Layer w0.21: U26.37@59.4,78.97 59.4,79.525
  Top Layer w0.25: L1.1@59.2,83.135 59.2,80.173 59.4,79.973 59.4,79.525
NetL2_1: L2.1 U26.26 | length 4.1
  Top Layer w0.2: U26.26@63.417,77.6 63.9,77.6 64.225,77.925 64.225,80.56 ; L2.1@65.35,81.685 L2.1@65.35,82.2
NetL3_1: L3.1 U26.40 | length 5.9
  Top Layer w0.15: L3.1@53.198,80.162 L3.1@53.35,80.01
  Top Layer w0.21: L3.1@53.35,80.275 53.635,79.99 55.41,79.99 57.765,79.99 58.2,79.555 U26.40@58.2,78.97
NetL4_1: L4.1 U26.23 | length 3.8
  Top Layer w0.15: L4.1@66.86,75.885 L4.1@66.86,76.4
  Top Layer w0.21: U26.23@63.17,76.4 63.725,76.4
  Top Layer w0.25: 63.725,76.4 66.5,76.4
NetL5_1: L5.1 U26.48 | length 7.2
  Top Layer w0.15: L5.1@51.118,74.448 L5.1@51.37,74.7 ; L5.1@51.59,74.585 L5.1@51.59,75.1
  Top Layer w0.21: 56.275,76.4 U26.48@56.83,76.4
  Top Layer w0.25: 51.325,75.6 51.775,76.05 54.7,76.05 55.05,76.4 56.275,76.4 ; L5.1@51.59,75.1 51.59,75.615
NetL6_1: L6.1 U26.19 | length 4.9
  Top Layer w0.21: U26.19@63.17,74.8 63.725,74.8
  Top Layer w0.25: 63.725,74.8 64.123,74.8 64.298,74.625 64.65,74.625 64.875,74.4 64.875,73.325 65.571,72.629 65.925,72.629 65.93,72.624 L6.1@65.93,72.025
NetL7_1: L7.1 U26.51 | length 7.4
  Top Layer w0.21: 56.275,75.2 U26.51@56.83,75.2
  Top Layer w0.25: L7.1@53.925,70.425 L7.1@53.925,70.669 ; L7.1@53.975,69.95 54.375,70.35 54.375,72.184 54.85,72.659 54.85,74.503 55.547,75.2 56.275,75.2
NetLD11_1: LD11.1 R210.2 | length 1
  Top Layer w0.2: LD11.1@42.887,68.077 R210.2@42.887,69.07
NetR2_2: R2.2 U26.56 | length 6.1
  Top Layer w0.15: R2.2@55.08,68.145 55.08,68.76 55.375,69.055 55.375,71.091 56.012,71.728 56.012,72.985 56.227,73.2 U26.56@56.755,73.2
NetR46_2: R46.2 U26.30 | length 2.8
  Top Layer w0.15: U26.30@62.2,78.97 62.2,80.87 62.532,81.202 62.532,81.43 R46.2@62.65,81.548
NetR57_2: R57.2 U26.12 | length 4.9
  Top Layer w0.21: U26.12@61.8,72.63 61.8,72.016 61.97,71.845
  Top Layer w0.3: 61.97,71.845 62.525,71.291 62.525,70.174 63.35,69.349 R57.2@63.35,68.4
NetR59_2: R59.2 U26.54 | length 8.5
  Top Layer w0.15: R59.2@52.98,68.145 52.98,68.64 53.15,68.81 54.236,68.81 54.875,69.449 54.875,71.298 55.512,71.935 55.512,73.335 56.177,74 U26.54@56.83,74
NetR60_2: R60.2 U26.55 | length 7.1
  Top Layer w0.15: R60.2@54.03,68.145 54.104,68.145 55.125,69.166 55.125,71.194 55.762,71.832 55.762,73.232 56.131,73.6 U26.55@56.83,73.6
NetR81_2: R81.2 U26.31 | length 5.7
  Top Layer w0.15: U26.31@61.8,78.97 61.8,80.973 61.95,81.123 61.95,83.81 62.038,83.898 R81.2@62.663,83.898
NetR112_2: R112.2 U10.G16 | length 0.9
  Top Layer w0.1: U10.G16@98.65,74.85 98.65,74.89 v4@99.028,75.268
  Bottom Layer w0.1: R112.2@99.025,74.875 v4(99.025,75.25)
NetR113_2: R113.2 U17.E9 | length 1.2
  Top Layer w0.28: U17.E9@115.327,76.073 115.365,76.073 115.54,76.248 R113.2@116.487,76.248
NetR161_1: R161.1 U10.C7 | length 2
  Top Layer w0.1: v4@91.05,78.55 v4(91.05,78.525) 91.05,78.45 U10.C7@91.45,78.05
  Bottom Layer w0.1: R161.1@90.6,79.65 90.6,79 v4@91.05,78.55
NetR162_1: R162.1 U10.C3 | length 4.7
  Top Layer w0.09: R162.1@85.15,80.2 85.289,80.339 86.531,80.339 86.948,79.922 86.948,79.083 87.004,79.028 87.004,78.893 87.155,78.742 87.155,78.728 87.328,78.555 87.745,78.555 U10.C3@88.25,78.05
NetR179_2: R179.2 U17.F9 | length 1.4
  Top Layer w0.3: U17.F9@115.327,75.273 115.35,75.25 115.443,75.25 115.895,74.798 R179.2@116.537,74.798
NetR196_2: R196.2 U10.T14 | length 4.2
  Top Layer w0.1: R196.2@96.55,63.625 96.55,67.15 U10.T14@97.05,67.65
NetTP9_1: TP9.1 U24.H5 | length 1.9
  Top Layer w0.09: v4@110.647,88.778 110.647,89.222 U24.H5@110.775,89.35
  Bottom Layer w0.09: v4(110.65,88.775) 110.65,87.6 TP9.1@110.7,87.55
NJTRST: U10.U2 | length 2.8
  Top Layer w0.09: 85.323,65.148 86.52,66.345 86.945,66.345 U10.U2@87.45,66.85
NRST: C33.2 R81.1 U10.N1 | length 48.8
  Top Layer w0.09: 81.733,66.05 83.863,68.18
  Top Layer w0.1: v3@75.425,70.347 C33.2@75.425,69.775 75.4,69.775 75.195,69.57 75.195,69.544 74.971,69.32 74.971,64.793 75.534,64.23 79.62,64.23 81.44,66.05 81.733,66.05 ; 83.863,68.18 83.863,68.201 85.446,69.784 85.775,69.784 86.019,70.028 86.628,70.028 U10.N1@86.65,70.05
  Top Layer w0.15: v3(61.604,84.33) 62.072,84.798 R81.1@62.663,84.798
  Bottom Layer w0.1: v3(61.604,84.33) 61.139,84.33 59.159,82.35 59.159,80.601 61.914,77.847 68.567,77.847 71.354,75.06 74.014,75.06 75.433,73.641 75.433,70.356 v3(75.424,70.347)
NRSTC1MS: D5.2 R27.1 R59.1 R272.1 U10.P2 | length 98.6
  Top Layer w0.1: R59.1@52.98,67.245 53.075,67.245 53.28,67.04 53.28,66.773 53.368,66.686 v1(53.368,66.564) ; v3(77.945,73.843) 80.125,76.023 v3(80.125,95.85) ; v4(85.325,68.485) 85.383,68.542 86.033,68.542 86.44,68.95 86.776,68.95 87.076,69.25 U10.P2@87.45,69.25
  Bottom Layer w0.1: v1(53.368,66.564) 53.682,66.942 cw(c54.009,66.67) 53.997,67.095 56.529,67.172 56.612,67.172 56.641,67.143 57.799,65.986 72.361,65.986 72.425,66.05 75.524,66.05 78.449,68.975 ; v3(77.945,73.843) 77.945,69.467 78.443,68.969 ; 78.444,68.975 84.826,68.975 84.899,68.903 v4(85.325,68.485) ; v3(80.125,95.85) 85.225,100.95 97.325,100.95 104.175,94.1 D5.2@104.175,90.77 ; v4@85.321,68.481 v4(85.325,68.485) ; R272.1@85.925,67.95 85.625,68.155 v4(85.325,68.485)
OSC32_IN: C86.1 U10.M2 X1.2 | length 14.5
  Top Layer w0.1: X1.2@76.525,65.9 C86.1@77.85,65.9 77.85,66.725 78,66.875 79.854,66.875 80.022,67.043 80.022,68.647 80.35,68.975 82.833,68.975 83.908,70.05 84.403,70.05 85.003,70.65 86.375,70.65 86.475,70.55 86.769,70.55 87.069,70.85 U10.M2@87.445,70.85
OSC32_OUT: R64.1 U10.M1 | length 9.2
  Top Layer w0.1: R64.1@79.6,67.425 79.734,67.559 79.652,67.559 79.652,68.56 80.267,69.175 82.75,69.175 83.825,70.25 84.32,70.25 84.92,70.85 U10.M1@86.65,70.85
PA1: U10.P14 | length 3.8
  Top Layer w0.1: U10.P14@97.05,69.25 97.082,69.218 97.082,69.068 v3(97.325,68.825)
  Bottom Layer w0.1: 96.84,65.801 96.84,68.34 v3(97.325,68.825)
PA2: U10.T10 | length 1.1
  Top Layer w0.09: v3@93.445,67.25 U10.T10@93.845,67.65
  Bottom Layer w0.09: 93.445,66.562 v3@93.445,67.075
  other v3: 93.45,67.075
PA3: U10.U12 | length 3
  Top Layer w0.09: 94.949,64.023 94.949,65.955 95.145,66.15 95.145,66.55 U10.U12@95.445,66.85
PA4: U10.T13 | length 1.1
  Top Layer w0.09: v3(95.85,67.075) 96.226,67.451 96.226,67.631 U10.T13@96.245,67.65
  Bottom Layer w0.09: 95.849,66.699 v3@95.849,67.074
PA5: U10.T11 | length 1.3
  Top Layer w0.09: v3(94.35,67.2) 94.61,67.46 94.61,67.615 U10.T11@94.645,67.65
  Bottom Layer w0.09: 94.25,66.563 94.35,66.663 v3(94.35,67.2)
PA6: U10.P11 | length 2.8
  Top Layer w0.09: v3@94.245,68.85 U10.P11@94.645,69.25
  Bottom Layer w0.09: v3(94.25,68.675) 94.7,68.225 94.7,66.66
PA7: U10.P12 | length 3.8
  Top Layer w0.09: v3@95.049,68.774 95.049,68.812 95.445,69.207 U10.P12@95.445,69.25
  Bottom Layer w0.09: v3@95.05,68.669 95.408,68.31 95.903,68.31 96.393,67.819 96.393,66.308
  other v3: 95.05,68.675
PA8: U10.U13 | length 2.6
  Top Layer w0.09: 95.747,64.406 95.747,65.916 95.845,66.013 95.845,66.45 U10.U13@96.245,66.85
PA9: U10.V10 | length 1.1
  Top Layer w0.09: 93.555,65.077 93.555,65.76 U10.V10@93.845,66.05
PA10: U10.W10 | length 0.9
  Top Layer w0.09: 93.85,64.356 U10.W10@93.85,65.25
PA11: U10.R8 | length 1.1
  Top Layer w0.09: v3(91.85,67.875) 91.85,67.888 92.219,68.258 92.219,68.419 U10.R8@92.25,68.45
  Bottom Layer w0.09: 91.57,67.596 v3(91.85,67.875)
PA12: U10.R9 | length 1.7
  Top Layer w0.09: v3@92.652,67.873 93.028,68.249 93.028,68.428 U10.R9@93.05,68.45
  Bottom Layer w0.09: 92.283,67.042 92.283,67.5 v3@92.65,67.867
  other v3: 92.65,67.875
PA13: U10.P9 | length 3.1
  Top Layer w0.09: v3@92.664,68.774 92.664,68.821 93.043,69.201 93.045,69.201 U10.P9@93.045,69.25
  Bottom Layer w0.09: 91.45,66.839 91.45,67.183 91.742,67.475 91.938,67.475 92.195,67.732 92.195,68.018 92.19,68.023 92.19,68.212 v3@92.65,68.672
  other v3: 92.65,68.675
PA14: U10.P8 | length 2.9
  Top Layer w0.09: v3(91.85,68.675) 91.85,68.743 92.053,68.946 92.053,69.01 92.245,69.202 U10.P8@92.245,69.25
  Bottom Layer w0.09: 91.029,66.851 91.029,67.365 91.395,67.731 91.395,68.018 91.392,68.021 91.392,68.224 v3@91.843,68.675
PA15: U10.U9 | length 1.8
  Top Layer w0.09: 92.56,65.265 92.56,65.451 92.645,65.536 92.645,66.45 U10.U9@93.045,66.85
PB0: U10.A9 | length 0.6
  Top Layer w0.1: U10.A9@93.05,79.65 93.05,80.281
PB1: U10.C8 | length 2.5
  Top Layer w0.1: 91.95,80.142 91.95,79.526 92.326,79.15 92.374,79.15 92.55,78.974 92.55,78.35 U10.C8@92.25,78.05
PB2: U10.C9 | length 1.9
  Top Layer w0.1: 92.55,79.706 92.55,79.303 92.75,79.103 92.75,78.343 U10.C9@93.043,78.05
PB3: U10.E8 | length 4.1
  Top Layer w0.09: v3@91.904,76.951 91.964,76.892 91.964,76.731 U10.E8@92.245,76.45
  Bottom Layer w0.09: 89.2,78.575 89.813,78.575 90.705,77.683 90.705,77.507 90.962,77.25 91.45,77.25 v3(91.85,76.85)
PB4: U10.B10 | length 1
  Top Layer w0.1: 93.55,79.728 93.55,79.15 U10.B10@93.85,78.85
PB5: U10.A10 | length 0.5
  Top Layer w0.1: U10.A10@93.85,79.65 93.85,80.175
PB6: U10.B9 | length 0.9
  Top Layer w0.1: 92.75,79.65 92.75,79.526 93.05,79.226 U10.B9@93.05,78.85
PB7: U10.B8 | length 1.8
  Top Layer w0.1: 91.75,80.396 91.75,79.35 U10.B8@92.25,78.85
PB8: U10.D8 | length 3.7
  Top Layer w0.1: v3@91.845,77.65 U10.D8@92.245,77.25
  Bottom Layer w0.1: 89.55,79.547 90.7,78.397 90.7,78.38 90.993,78.087 91.107,78.087 91.4,77.795 91.4,77.709 91.459,77.65 v3(91.85,77.65)
PB9: U10.E7 | length 3.4
  Top Layer w0.09: v3@91.07,76.951 91.07,76.887 91.445,76.512 U10.E7@91.445,76.45
  Bottom Layer w0.09: 88.9,78.155 89.155,77.9 89.155,77.888 89.313,77.73 89.682,77.73 90.107,77.305 90.283,77.305 90.595,76.993 90.595,76.903 90.648,76.85 v3(91.05,76.85)
PB10: U10.A8 | length 0.6
  Top Layer w0.1: U10.A8@92.25,79.65 92.25,80.282
PB11: U10.D7 | length 2.8
  Top Layer w0.1: v4@91.025,77.65 v4(91.05,77.65) U10.D7@91.45,77.25
  Bottom Layer w0.1: 89.475,79.25 89.475,79.225 v4(91.05,77.65)
PB12: U10.B16 | length 1.2
  Top Layer w0.09: U10.B16@98.65,78.85 98.95,79.15 98.95,79.937
PB13: U10.C15 | length 1.9
  Top Layer w0.09: U10.C15@97.845,78.05 97.845,78.395 98.135,78.685 98.135,78.718 98.145,78.728 98.145,79.023 98.355,79.233 98.355,79.755
PB14: U10.E16 | length 1.9
  Top Layer w0.1: U10.E16@98.65,76.45 98.65,76.473 99.005,76.828 v3@99.005,76.85
  Bottom Layer w0.1: v3@99.005,76.85 99.062,76.907 99.062,77.157 99.408,77.503 99.408,78.078
  other v3: 99,76.85
PB15: U10.W3 | length 0.6
  Top Layer w0.09: 88.245,64.7 88.245,65.245 U10.W3@88.25,65.25
PC0: U10.P10 | length 2.9
  Top Layer w0.09: v3@93.428,68.775 93.428,68.804 93.845,69.221 U10.P10@93.845,69.25
  Bottom Layer w0.09: 93,66.609 93,68.215 93.45,68.665 v3(93.45,68.675)
PC1: U10.V9 | length 1
  Top Layer w0.09: 92.75,65.128 92.75,65.372 93.045,65.667 U10.V9@93.045,66.05
PC2: U10.V8 | length 1.1
  Top Layer w0.09: 91.945,65.05 91.945,65.75 U10.V8@92.245,66.05
PC3: U10.V5 | length 1.4
  Top Layer w0.09: 89.349,64.884 89.349,65.555 U10.V5@89.845,66.05
PC4: U10.T6 | length 1.1
  Top Layer w0.09: v3@90.283,67.201 90.283,67.242 90.645,67.603 U10.T6@90.645,67.65
  Bottom Layer w0.09: 90.25,66.569 v3(90.25,67.075)
PC5: U10.R7 | length 1.9
  Top Layer w0.09: v3(91.05,67.875) 91.426,68.251 91.426,68.426 U10.R7@91.45,68.45
  Bottom Layer w0.09: 90.633,66.839 90.633,67.453 v3@91.05,67.869
PC6: U10.T7 | length 3.7
  Top Layer w0.09: 90.145,64.512 90.145,65.512 90.338,65.704 90.338,66.155 90.525,66.342 90.545,66.342 91.084,66.881 91.084,67.243 91.445,67.603 U10.T7@91.445,67.65
PC7: U10.U6 | length 2.1
  Top Layer w0.09: 89.555,65.2 89.555,65.408 89.902,65.755 89.972,65.755 90.145,65.928 90.145,66.172 90.142,66.175 90.142,66.347 U10.U6@90.645,66.85
PC8: U10.V6 | length 1.2
  Top Layer w0.09: 90.355,64.999 90.355,65.453 90.555,65.653 90.555,65.667 90.65,65.762 U10.V6@90.65,66.05
PC9: U10.W6 | length 1.1
  Top Layer w0.09: 90.65,64.191 U10.W6@90.65,65.25
PC10: U10.U7 | length 2.7
  Top Layer w0.09: 90.96,64.366 90.96,66.03 91.45,66.521 U10.U7@91.45,66.85
PC11: U10.U5 | length 1.2
  Top Layer w0.09: v4(89.45,66.275) 89.826,66.651 89.826,66.826 U10.U5@89.85,66.85
  Bottom Layer w0.09: 89.448,65.866 89.45,65.868 v4(89.45,66.275)
PC12: U10.V4 | length 1.1
  Top Layer w0.09: 88.75,65.055 88.75,65.755 U10.V4@89.045,66.05
PCIE_CLKINN: U10.W13 | length 0.8
  Top Layer w0.1: 96.25,64.45 U10.W13@96.25,65.25
PCIE_CLKINP: U10.V13 | length 1.8
  Top Layer w0.09: 95.955,64.369 95.955,65.372 96.036,65.453 96.036,65.841 U10.V13@96.245,66.05
PD0: U10.B11 | length 1
  Top Layer w0.1: 94.35,79.774 94.35,79.391 94.65,79.091 U10.B11@94.65,78.85
PD1: U10.A12 | length 0.5
  Top Layer w0.1: U10.A12@95.45,79.65 95.45,80.14
PD2: U10.D9 | length 1
  Top Layer w0.09: v3@92.645,77.65 U10.D9@93.045,77.25
  Bottom Layer w0.09: v3(92.65,77.65) 92.65,78.132
PD3: U10.C10 | length 1.9
  Top Layer w0.1: 93.35,79.723 93.35,78.726 93.344,78.72 93.344,78.556 U10.C10@93.85,78.05
PD4: U10.E10 | length 2.4
  Top Layer w0.09: v3@93.475,76.951 93.475,76.882 93.845,76.512 U10.E10@93.845,76.45
  Bottom Layer w0.09: v3(93.45,76.85) 93.795,77.195 93.795,78.463
PD5: U10.D11 | length 1.4
  Top Layer w0.09: U10.D11@94.645,77.25 94.695,77.25 95.095,77.65 v3@95.145,77.65
  Bottom Layer w0.09: v3(95.05,77.65) 95.05,78.343
PD6: U10.E12 | length 2.3
  Top Layer w0.09: U10.E12@95.445,76.45 95.445,76.5 95.5,76.5 95.746,76.746 95.746,76.914 v3@95.805,76.973
  Bottom Layer w0.09: 95.477,78.337 95.477,77.223 v3(95.85,76.85)
PD7: U10.E11 | length 2.4
  Top Layer w0.09: U10.E11@94.645,76.45 94.645,76.501 95.068,76.925 v3@95.068,76.986
  Bottom Layer w0.09: 94.563,78.294 94.563,77.337 v3(95.05,76.85)
PD8: U10.A11 | length 0.7
  Top Layer w0.1: U10.A11@94.65,79.65 94.65,80.355
PD9: U10.E9 | length 2
  Top Layer w0.09: v3@92.645,76.951 92.645,76.903 93.045,76.503 U10.E9@93.045,76.45
  Bottom Layer w0.09: v3(92.65,76.85) 93.076,77.276 93.076,77.961
PD10: U10.C11 | length 2
  Top Layer w0.1: 94.15,79.83 94.15,79.067 94.293,78.924 94.293,78.407 U10.C11@94.65,78.05
PD11: U10.D10 | length 1
  Top Layer w0.09: v3@93.445,77.65 U10.D10@93.845,77.25
  Bottom Layer w0.09: v3(93.45,77.65) 93.45,78.114
PD12: U10.A16 | length 0.4
  Top Layer w0.09: U10.A16@98.65,79.65 98.65,80.025
PD13: U10.D16 | length 1.1
  Top Layer w0.09: U10.D16@98.65,77.25 v3(99.05,77.65)
  Bottom Layer w0.09: 99.025,78.125 99.05,78.1 v3(99.05,77.65) v3@99.075,77.675
PE0: U10.A13 | length 0.5
  Top Layer w0.09: U10.A13@96.245,79.65 96.245,80.175
PE1: U10.B13 | length 1.3
  Top Layer w0.09: 95.945,80.025 95.945,79.153 U10.B13@96.25,78.85
PE2: U10.C13 | length 2.5
  Top Layer w0.1: 95.75,80.39 95.75,78.802 96.25,78.302 U10.C13@96.25,78.05
PE3: U10.D14 | length 3.3
  Top Layer w0.09: U10.D14@97.05,77.25 97.05,77.307 97.122,77.379 97.122,77.401 97.565,77.843 97.565,77.918 97.555,77.928 97.555,79.772 97.647,79.864 97.647,80.317
PE4: U10.D13 | length 3.5
  Top Layer w0.09: U10.D13@96.245,77.25 96.295,77.25 96.573,77.528 96.573,79.045 96.471,79.146 96.471,79.454 96.545,79.528 96.545,80.521
PE5: U10.E13 | length 2.2
  Top Layer w0.09: U10.E13@96.245,76.45 96.245,76.481 96.697,76.934 v3@96.697,76.971
  Bottom Layer w0.09: v3(96.65,76.85) 96.65,78.344
PF0: U10.R10 | length 2.2
  Top Layer w0.09: v3(93.45,67.875) 93.45,67.887 93.82,68.257 93.82,68.42 U10.R10@93.85,68.45
  Bottom Layer w0.09: v3(93.45,67.875) 93.8,67.525 93.8,66.525
PF1: U10.U8 | length 2.1
  Top Layer w0.09: 91.745,64.985 91.745,66.35 U10.U8@92.245,66.85
PF2: U10.R11 | length 2.3
  Top Layer w0.09: v3(94.245,67.875) 94.258,67.875 94.63,68.247 94.63,68.43 U10.R11@94.65,68.45
  Bottom Layer w0.09: 94,66.4 94,67.63 v3(94.245,67.875)
PF3: U10.T9 | length 1.3
  Top Layer w0.09: v3@92.67,67.198 92.67,67.234 93.045,67.609 U10.T9@93.045,67.65
  Bottom Layer w0.09: 92.655,66.421 v3@92.655,67.07
  other v3: 92.65,67.075
PF4: U10.W5 | length 1.1
  Top Layer w0.09: 89.85,64.191 U10.W5@89.85,65.25
PF5: U10.P7 | length 3.5
  Top Layer w0.09: v3@91.046,68.752 91.046,68.802 91.445,69.2 U10.P7@91.445,69.25
  Bottom Layer w0.09: 88.907,67.49 89.572,67.49 89.814,67.732 89.814,68.035 90.041,68.263 90.638,68.263 v3(91.05,68.675)
PF6: U10.R5 | length 1.4
  Top Layer w0.09: v3(89.45,67.875) 89.826,68.251 89.826,68.431 U10.R5@89.845,68.45
  Bottom Layer w0.09: 88.822,67.875 v3(89.45,67.875)
PF7: U10.R6 | length 1.9
  Top Layer w0.09: v3(90.25,67.875) 90.279,67.875 90.641,68.236 90.641,68.441 U10.R6@90.65,68.45
  Bottom Layer w0.09: 89.875,66.925 89.875,67.488 90.25,67.863 v3(90.25,67.875)
PF8: U10.T5 | length 1.5
  Top Layer w0.09: v3@89.45,67.177 89.45,67.213 89.845,67.608 U10.T5@89.845,67.65
  Bottom Layer w0.09: 88.978,66.362 88.978,66.603 v3(89.45,67.075)
PF9: U10.U4 | length 1.9
  Top Layer w0.09: 88.56,65.172 88.56,66.351 89.045,66.836 U10.U4@89.045,66.85
PF10: U10.P6 | length 2
  Top Layer w0.09: v3@90.245,68.85 U10.P6@90.645,69.25
  Bottom Layer w0.09: 88.93,68.33 89.593,68.33 89.938,68.675 v3(90.25,68.675)
PF11: U10.R4 | length 5.1
  Top Layer w0.09: 86.03,64.787 86.03,65.047 86.528,65.545 86.694,65.545 87.155,66.006 87.155,66.207 87.283,66.335 87.369,66.335 87.965,66.931 87.965,66.984 88.336,67.355 88.372,67.355 88.545,67.528 88.545,67.611 88.765,67.831 88.765,68.165 U10.R4@89.05,68.45
PF12: U10.J5 | length 3.6
  Top Layer w0.1: 86.443,73.75 88.829,73.75 88.842,73.737 89.386,73.737 89.845,73.278 U10.J5@89.845,73.25
PF13: U10.G6 | length 4.8
  Top Layer w0.09: U10.G6@90.65,74.85 90.991,75.191 90.991,75.207 91.001,75.218 v3@91.07,75.218
  Bottom Layer w0.09: 87.525,74.04 89.353,74.04 89.905,74.592 89.905,74.768 90.142,75.005 90.393,75.005 90.738,75.35 v3(91.05,75.35)
PF14: U10.F5 | length 1.6
  Top Layer w0.1: v3@89.44,75.968 89.483,75.968 89.802,75.65 U10.F5@89.845,75.65
  Bottom Layer w0.1: 88.487,76.4 88.803,76.4 89.153,76.05 v3@89.45,76.05
  other v3: 89.45,76.075
PF15: U10.G5 | length 3
  Top Layer w0.1: U10.G5@89.85,74.85 89.888,74.888 89.888,74.988 v3(90.25,75.35)
  Bottom Layer w0.1: 88.106,74.984 89.84,74.984 90.206,75.35 v3(90.25,75.35)
PG0: U10.W4 | length 1
  Top Layer w0.09: 89.05,64.282 U10.W4@89.05,65.25
PG1: U10.T3 | length 3.4
  Top Layer w0.09: 85.691,65.784 86.461,66.555 86.825,66.555 86.881,66.555 87.155,66.829 87.155,66.972 87.328,67.145 87.745,67.145 U10.T3@88.25,67.65
PG2: U10.T4 | length 4.1
  Top Layer w0.09: 87.643,64.191 87.643,64.912 87.77,65.04 87.77,65.589 87.95,65.769 87.95,66.167 88.18,66.397 88.337,66.397 88.699,66.759 88.699,67.299 U10.T4@89.05,67.65
PG3: U10.U3 | length 2.2
  Top Layer w0.09: 87.155,65.128 87.155,65.372 87.383,65.6 87.417,65.6 87.75,65.933 87.75,66.347 88.25,66.847 U10.U3@88.25,66.85
PG4: U10.V3 | length 0.8
  Top Layer w0.09: 87.96,65.377 88.253,65.671 88.253,66.047 U10.V3@88.25,66.05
